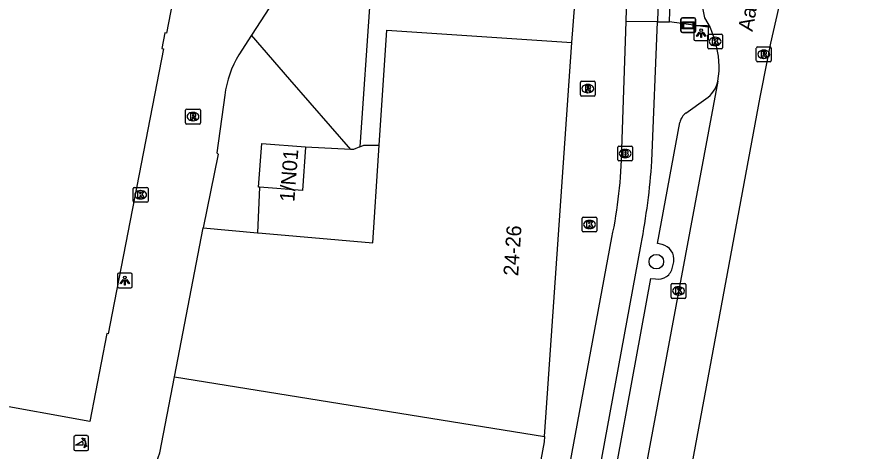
# Model space of a CAD drawing. Extents: x 161402 to 161933, y 381650 to 382313.
# Drawn here: x 161869.9 to 161926.7, y 382046.6 to 382075.9 of the extents above; entities that cross this region are included whole.
import ezdxf

# ---------------------------------------------------------------- set-up
doc = ezdxf.new("R2010")
doc.units = 0
for name, color, linetype in [('IMGEO_Boom', 7, 'Continuous'), ('IMGEO_Brandkraan', 7, 'Continuous'), ('IMGEO_Fietspad_gesloten', 7, 'Continuous'), ('IMGEO_Fietspad_open', 7, 'Continuous'), ('IMGEO_Kolk', 7, 'Continuous'), ('IMGEO_Lichtpunt', 7, 'Continuous'), ('IMGEO_Openbare_ruimte_label', 7, 'Continuous'), ('IMGEO_OVBaan_gesloten', 7, 'Continuous'), ('IMGEO_Pand', 7, 'Continuous'), ('IMGEO_Pand_nummerreeks', 7, 'Continuous'), ('IMGEO_Parkeervlak_open', 7, 'Continuous'), ('IMGEO_Poller', 7, 'Continuous'), ('IMGEO_Reclamebord', 7, 'Continuous'), ('IMGEO_Rijbaan_lokaal_gesloten', 7, 'Continuous'), ('IMGEO_Rijbaan_lokaal_open', 7, 'Continuous'), ('IMGEO_Rioolput', 7, 'Continuous'), ('IMGEO_Verkeerseiland_open', 7, 'Continuous'), ('IMGEO_Voetpad_open', 7, 'Continuous')]:
    doc.layers.add(name, color=color, linetype=linetype)

msp = doc.modelspace()

# ---------------------------------------------------------------- linework, layer by layer
at = {"layer": 'IMGEO_Boom'}
msp.add_circle((161913.065, 382059.379), 0.489, dxfattribs=at)
at = {"layer": 'IMGEO_Brandkraan'}
for p, q in [((161910.461, 382066.251), (161910.461, 382067.103)), ((161910.536, 382067.177), (161911.388, 382067.177)), ((161910.949, 382066.957), (161910.974, 382066.957)), ((161911.462, 382067.103), (161911.462, 382066.251)), ((161910.972, 382066.397), (161910.947, 382066.397)), ((161911.388, 382066.177), (161910.536, 382066.177))]:
    msp.add_line(p, q, dxfattribs=at)
for points in [[(161910.461, 382066.251), (161910.461, 382067.103)], [(161910.536, 382067.177), (161911.388, 382067.177)], [(161911.462, 382067.103), (161911.462, 382066.251)], [(161910.809, 382066.877), (161910.809, 382066.477), (161911.022, 382066.477)], [(161911.04, 382066.877), (161910.809, 382066.877)], [(161910.988, 382066.796), (161910.934, 382066.796), (161910.934, 382066.72)], [(161910.934, 382066.72), (161910.987, 382066.72)], [(161910.996, 382066.644), (161910.934, 382066.644), (161910.934, 382066.563)], [(161910.934, 382066.563), (161910.996, 382066.563)], [(161911.388, 382066.177), (161910.536, 382066.177)]]:
    msp.add_lwpolyline(points, dxfattribs=at)
for centre, radius, start, end in [((161910.538, 382067.101), 0.0765, 91.552, 178.448), ((161910.538, 382067.101), 0.0765, 91.552, 178.448), ((161911.386, 382067.101), 0.0765, 1.552, 88.448), ((161911.386, 382067.101), 0.0765, 1.552, 88.448), ((161910.989, 382066.758), 0.0379, 267.8285, 90.9355), ((161910.997, 382066.603), 0.0404, 269.8759, 90.5077), ((161911.028, 382066.728), 0.251, 268.6676, 293.5347), ((161911.044, 382066.732), 0.145, 59.4692, 91.5367), ((161911.069, 382066.779), 0.0922, 285.5137, 58.1501), ((161911.074, 382066.587), 0.105, 301.3115, 78.989), ((161910.538, 382066.253), 0.0765, 181.552, 268.448), ((161910.538, 382066.253), 0.0765, 181.552, 268.448), ((161911.386, 382066.253), 0.0765, 271.552, 358.448), ((161911.386, 382066.253), 0.0765, 271.552, 358.448)]:
    msp.add_arc(centre, radius, start, end, dxfattribs=at)
for centre, major_axis, ratio, start_param, end_param in [((161910.948, 382066.677), (-0.387, 0.002), 0.722429, 4.712389, 7.853982), ((161910.973, 382066.677), (-0.39, 0.002), 0.717154, 1.570796, 4.712389)]:
    msp.add_ellipse(centre, major_axis=major_axis, ratio=ratio, start_param=start_param, end_param=end_param, dxfattribs=at)
at = {"layer": 'IMGEO_Fietspad_gesloten'}
for points in [[(161910.741, 382066.974), (161911.019, 382075.595)], [(161913.149, 382075.567), (161911.019, 382075.595)], [(161912.769, 382066.155), (161913.149, 382075.567)], [(161887.89, 381941.593), (161898.752, 382000), (161905.702, 382037.375), (161910.061, 382061.001)], [(161869.899, 381834.602), (161881.54, 381896.271), (161882.623, 381902.093), (161888.398, 381933.147), (161890.059, 381942.083), (161900.83, 382000), (161908.061, 382038.88), (161912.039, 382060.567)]]:
    msp.add_lwpolyline(points, dxfattribs=at)
for centre, radius, start, end in [((161879.075, 382067.554), 31.672, 348.0592, 358.9509), ((161864.289, 382069.647), 48.606, 349.2338, 355.8806)]:
    msp.add_arc(centre, radius, start, end, dxfattribs=at)
at = {"layer": 'IMGEO_Fietspad_open'}
for points in [[(161911.019, 382075.595), (161911.485, 382092.573), (161911.516, 382094.566), (161911.423, 382100.579), (161910.052, 382144.744)], [(161912.16, 382144.813), (161912.252, 382141.473), (161913.518, 382100.778), (161913.546, 382089.832), (161913.149, 382075.567)]]:
    msp.add_lwpolyline(points, dxfattribs=at)
at = {"layer": 'IMGEO_Kolk'}
for p, q in [((161916.532, 382073.821), (161916.532, 382074.673)), ((161916.607, 382074.747), (161917.459, 382074.747)), ((161917.02, 382074.527), (161917.045, 382074.527)), ((161917.533, 382074.673), (161917.533, 382073.821)), ((161917.459, 382073.747), (161916.607, 382073.747)), ((161917.043, 382073.967), (161917.018, 382073.967)), ((161877.739, 382063.468), (161877.739, 382064.32)), ((161877.814, 382064.394), (161878.666, 382064.394)), ((161878.227, 382064.174), (161878.252, 382064.174)), ((161878.74, 382064.32), (161878.74, 382063.468)), ((161878.25, 382063.614), (161878.225, 382063.614)), ((161878.666, 382063.394), (161877.814, 382063.394)), ((161908.13, 382062.389), (161908.982, 382062.389)), ((161908.055, 382061.463), (161908.055, 382062.315)), ((161908.543, 382062.169), (161908.568, 382062.169)), ((161909.056, 382062.315), (161909.056, 382061.463)), ((161908.982, 382061.389), (161908.13, 382061.389)), ((161908.566, 382061.609), (161908.541, 382061.609)), ((161914.066, 382056.977), (161914.066, 382057.829)), ((161914.141, 382057.903), (161914.993, 382057.903)), ((161915.067, 382057.829), (161915.067, 382056.977)), ((161914.554, 382057.683), (161914.579, 382057.683)), ((161914.993, 382056.903), (161914.141, 382056.903)), ((161914.577, 382057.123), (161914.552, 382057.123))]:
    msp.add_line(p, q, dxfattribs=at)
for points in [[(161916.532, 382073.821), (161916.532, 382074.673)], [(161916.607, 382074.747), (161917.459, 382074.747)], [(161916.853, 382074.447), (161916.976, 382074.447), (161916.976, 382074.296), (161917.106, 382074.447), (161917.27, 382074.447), (161917.124, 382074.296), (161917.277, 382074.047), (161917.125, 382074.047), (161917.04, 382074.211), (161916.976, 382074.144), (161916.976, 382074.047), (161916.853, 382074.047), (161916.853, 382074.447)], [(161917.533, 382074.673), (161917.533, 382073.821)], [(161917.459, 382073.747), (161916.607, 382073.747)], [(161877.739, 382063.468), (161877.739, 382064.32)], [(161877.814, 382064.394), (161878.666, 382064.394)], [(161878.06, 382064.094), (161878.183, 382064.094), (161878.183, 382063.943), (161878.313, 382064.094), (161878.477, 382064.094), (161878.331, 382063.943), (161878.484, 382063.694), (161878.332, 382063.694), (161878.247, 382063.858), (161878.183, 382063.791), (161878.183, 382063.694), (161878.06, 382063.694), (161878.06, 382064.094)], [(161878.74, 382064.32), (161878.74, 382063.468)], [(161878.666, 382063.394), (161877.814, 382063.394)], [(161908.13, 382062.389), (161908.982, 382062.389)], [(161908.055, 382061.463), (161908.055, 382062.315)], [(161908.376, 382062.089), (161908.499, 382062.089), (161908.499, 382061.938), (161908.629, 382062.089), (161908.793, 382062.089), (161908.647, 382061.938), (161908.8, 382061.689), (161908.648, 382061.689), (161908.563, 382061.853), (161908.499, 382061.786), (161908.499, 382061.689), (161908.376, 382061.689), (161908.376, 382062.089)], [(161909.056, 382062.315), (161909.056, 382061.463)], [(161908.982, 382061.389), (161908.13, 382061.389)], [(161914.066, 382056.977), (161914.066, 382057.829)], [(161914.141, 382057.903), (161914.993, 382057.903)], [(161915.067, 382057.829), (161915.067, 382056.977)], [(161914.387, 382057.603), (161914.51, 382057.603), (161914.51, 382057.452), (161914.64, 382057.603), (161914.804, 382057.603), (161914.658, 382057.452), (161914.811, 382057.203), (161914.659, 382057.203), (161914.574, 382057.367), (161914.51, 382057.3), (161914.51, 382057.203), (161914.387, 382057.203), (161914.387, 382057.603)], [(161914.993, 382056.903), (161914.141, 382056.903)]]:
    msp.add_lwpolyline(points, dxfattribs=at)
for centre, start, end in [((161916.609, 382074.671), 91.552, 178.448), ((161916.609, 382074.671), 91.552, 178.448), ((161917.457, 382074.671), 1.552, 88.448), ((161917.457, 382074.671), 1.552, 88.448), ((161916.609, 382073.823), 181.552, 268.448), ((161916.609, 382073.823), 181.552, 268.448), ((161917.457, 382073.823), 271.552, 358.448), ((161917.457, 382073.823), 271.552, 358.448), ((161877.816, 382064.318), 91.552, 178.448), ((161877.816, 382064.318), 91.552, 178.448), ((161878.664, 382064.318), 1.552, 88.448), ((161878.664, 382064.318), 1.552, 88.448), ((161877.816, 382063.47), 181.552, 268.448), ((161877.816, 382063.47), 181.552, 268.448), ((161878.664, 382063.47), 271.552, 358.448), ((161878.664, 382063.47), 271.552, 358.448), ((161908.132, 382062.313), 91.552, 178.448), ((161908.132, 382062.313), 91.552, 178.448), ((161908.98, 382062.313), 1.552, 88.448), ((161908.98, 382062.313), 1.552, 88.448), ((161908.132, 382061.465), 181.552, 268.448), ((161908.132, 382061.465), 181.552, 268.448), ((161908.98, 382061.465), 271.552, 358.448), ((161908.98, 382061.465), 271.552, 358.448), ((161914.143, 382057.827), 91.552, 178.448), ((161914.143, 382057.827), 91.552, 178.448), ((161914.991, 382057.827), 1.552, 88.448), ((161914.991, 382057.827), 1.552, 88.448), ((161914.143, 382056.979), 181.552, 268.448), ((161914.143, 382056.979), 181.552, 268.448), ((161914.991, 382056.979), 271.552, 358.448), ((161914.991, 382056.979), 271.552, 358.448)]:
    msp.add_arc(centre, 0.0765, start, end, dxfattribs=at)
for centre, major_axis, ratio, start_param, end_param in [((161917.019, 382074.247), (-0.387, 0.002), 0.722429, 4.712389, 7.853982), ((161917.044, 382074.247), (-0.39, 0.002), 0.717154, 1.570796, 4.712389), ((161878.226, 382063.894), (-0.387, 0.002), 0.722429, 4.712389, 7.853982), ((161878.251, 382063.894), (-0.39, 0.002), 0.717154, 1.570796, 4.712389), ((161908.542, 382061.889), (-0.387, 0.002), 0.722429, 4.712389, 7.853982), ((161908.567, 382061.889), (-0.39, 0.002), 0.717154, 1.570796, 4.712389), ((161914.553, 382057.403), (-0.387, 0.002), 0.722429, 4.712389, 7.853982), ((161914.578, 382057.403), (-0.39, 0.002), 0.717154, 1.570796, 4.712389)]:
    msp.add_ellipse(centre, major_axis=major_axis, ratio=ratio, start_param=start_param, end_param=end_param, dxfattribs=at)
at = {"layer": 'IMGEO_Lichtpunt'}
for p, q in [((161915.593, 382075.209), (161915.593, 382074.402)), ((161915.593, 382075.209), (161915.593, 382074.402)), ((161916.495, 382075.304), (161915.687, 382075.304)), ((161916.495, 382075.304), (161915.687, 382075.304)), ((161916.589, 382074.402), (161916.589, 382075.209)), ((161916.589, 382074.402), (161916.589, 382075.209)), ((161915.687, 382074.308), (161916.495, 382074.308)), ((161915.687, 382074.308), (161916.495, 382074.308)), ((161876.677, 382058.507), (161876.677, 382057.7)), ((161876.677, 382058.507), (161876.677, 382057.7)), ((161877.579, 382058.602), (161876.771, 382058.602)), ((161877.579, 382058.602), (161876.771, 382058.602)), ((161877.673, 382057.7), (161877.673, 382058.507)), ((161877.673, 382057.7), (161877.673, 382058.507)), ((161876.771, 382057.606), (161877.579, 382057.606)), ((161876.771, 382057.606), (161877.579, 382057.606))]:
    msp.add_line(p, q, dxfattribs=at)
for points in [[(161915.967, 382074.873), (161916.006, 382074.845), (161915.818, 382074.583), (161915.78, 382074.61), (161915.967, 382074.873)], [(161916.179, 382074.845), (161916.217, 382074.872), (161916.404, 382074.61), (161916.365, 382074.582), (161916.179, 382074.845)], [(161916.069, 382074.825), (161916.116, 382074.825), (161916.116, 382074.503), (161916.069, 382074.503), (161916.069, 382074.825)], [(161877.051, 382058.171), (161877.09, 382058.143), (161876.902, 382057.881), (161876.864, 382057.908), (161877.051, 382058.171)], [(161877.153, 382058.123), (161877.2, 382058.123), (161877.2, 382057.801), (161877.153, 382057.801), (161877.153, 382058.123)], [(161877.263, 382058.143), (161877.301, 382058.17), (161877.488, 382057.908), (161877.449, 382057.88), (161877.263, 382058.143)]]:
    msp.add_lwpolyline(points, dxfattribs=at)
for centre in [(161916.092, 382075.007), (161877.176, 382058.305)]:
    msp.add_circle(centre, 0.0994, dxfattribs=at)
for centre, start, end in [((161915.687, 382075.209), 90, 180), ((161915.687, 382075.209), 90, 180), ((161916.495, 382075.209), 0, 90), ((161916.495, 382075.209), 0, 90), ((161915.687, 382074.402), 180, 270), ((161915.687, 382074.402), 180, 270), ((161916.495, 382074.402), 270, 0), ((161916.495, 382074.402), 270, 360), ((161876.771, 382058.507), 90, 180), ((161876.771, 382058.507), 90, 180), ((161877.579, 382058.507), 0, 90), ((161877.579, 382058.507), 0, 90), ((161876.771, 382057.7), 180, 270), ((161876.771, 382057.7), 180, 270), ((161877.579, 382057.7), 270, 0), ((161877.579, 382057.7), 270, 360)]:
    msp.add_arc(centre, 0.0946, start, end, dxfattribs=at)
at = {"layer": 'IMGEO_OVBaan_gesloten'}
msp.add_lwpolyline([(161894.174, 381930.698), (161920.066, 382070.485), (161920.568, 382072.989), (161920.797, 382074.121), (161926.695, 382099.95)], dxfattribs=at)
at = {"layer": 'IMGEO_Pand'}
for points in [[(161881.604, 382083.709), (161880.846, 382079.728), (161880.941, 382079.709), (161879.984, 382074.802), (161879.866, 382074.825), (161879.674, 382073.772), (161879.777, 382073.754), (161876.327, 382055.897), (161876.056, 382054.517), (161875.966, 382054.535), (161874.803, 382048.597), (161867.831, 382049.852)], [(161894.356, 382067.242), (161894.871, 382075.011), (161907.356, 382074.185)], [(161905.504, 382047.572), (161907.356, 382074.185)], [(161886.126, 382061.332), (161886.444, 382061.304), (161893.92, 382060.648), (161894.311, 382066.556), (161894.356, 382067.242)], [(161886.272, 382064.4), (161886.197, 382064.406), (161886.417, 382067.362), (161889.384, 382067.141), (161889.381, 382067.098)], [(161889.381, 382067.098), (161889.164, 382064.185), (161886.272, 382064.4)], [(161880.537, 382051.6), (161882.474, 382061.653)], [(161882.474, 382061.653), (161886.126, 382061.332)], [(161878.423, 382043.323), (161879.548, 382046.468), (161880.537, 382051.6)], [(161880.537, 382051.6), (161905.504, 382047.572)], [(161905.504, 382047.572), (161905.48, 382047.22), (161903.899, 382038.59)]]:
    msp.add_lwpolyline(points, dxfattribs=at)
at = {"layer": 'IMGEO_Parkeervlak_open'}
for points in [[(161915.065, 382069.413), (161916.415, 382070.367)], [(161913.448, 382060.543), (161913.141, 382060.602), (161914.659, 382068.781)], [(161914.151, 382059.011), (161914.248, 382059.368)], [(161909.441, 382038.888), (161909.164, 382038.94), (161912.699, 382058.251), (161913.017, 382058.21)]]:
    msp.add_lwpolyline(points, dxfattribs=at)
for centre, radius, start, end in [((161915.343, 382071.952), 1.914, 304.054, 348.2569), ((161915.635, 382068.6), 0.993, 125.0548, 169.5114), ((161913.206, 382059.518), 1.053, 351.8071, 76.691), ((161913.193, 382059.164), 0.97, 259.5654, 350.9054)]:
    msp.add_arc(centre, radius, start, end, dxfattribs=at)
at = {"layer": 'IMGEO_Poller'}
for p, q in [((161874.634, 382047.632), (161873.826, 382047.632)), ((161874.634, 382047.632), (161873.826, 382047.632)), ((161873.732, 382047.537), (161873.732, 382046.73)), ((161873.732, 382047.537), (161873.732, 382046.73)), ((161874.728, 382046.73), (161874.728, 382047.537)), ((161874.728, 382046.73), (161874.728, 382047.537)), ((161873.826, 382046.635), (161874.634, 382046.635)), ((161873.826, 382046.635), (161874.634, 382046.635))]:
    msp.add_line(p, q, dxfattribs=at)
for points in [[(161874.367, 382046.988), (161873.854, 382046.988), (161874.284, 382047.263)], [(161874.411, 382047.361), (161874.399, 382047.288), (161874.274, 382047.493)], [(161874.274, 382047.493), (161874.505, 382047.427), (161874.434, 382047.395)], [(161874.427, 382046.816), (161874.493, 382047.047), (161874.523, 382046.979)], [(161874.559, 382046.952), (161874.631, 382046.941), (161874.427, 382046.816)]]:
    msp.add_lwpolyline(points, dxfattribs=at)
for centre, radius, start, end in [((161873.826, 382047.537), 0.0946, 90, 180), ((161873.826, 382047.537), 0.0946, 90, 180), ((161874.634, 382047.537), 0.0946, 0, 90), ((161874.634, 382047.537), 0.0946, 0, 90), ((161874.039, 382047.038), 0.332, 351.3247, 42.4854), ((161874.053, 382047.048), 0.476, 351.7527, 41.1691), ((161874.053, 382047.048), 0.516, 349.3569, 42.2912), ((161873.826, 382046.73), 0.0946, 180, 270), ((161873.826, 382046.73), 0.0946, 180, 270), ((161874.634, 382046.73), 0.0946, 270, 0), ((161874.634, 382046.73), 0.0946, 270, 0)]:
    msp.add_arc(centre, radius, start, end, dxfattribs=at)
at = {"layer": 'IMGEO_Reclamebord'}
for p, q in [((161914.729, 382074.94), (161914.729, 382075.74)), ((161914.729, 382075.74), (161914.729, 382074.94)), ((161914.829, 382075.84), (161915.619, 382075.84)), ((161915.619, 382075.84), (161914.829, 382075.84)), ((161915.719, 382075.74), (161915.719, 382074.94)), ((161915.719, 382074.94), (161915.719, 382075.74)), ((161915.619, 382074.84), (161914.829, 382074.84)), ((161914.829, 382074.84), (161915.619, 382074.84))]:
    msp.add_line(p, q, dxfattribs=at)
for points in [[(161914.83, 382075.572), (161915.618, 382075.572), (161915.618, 382075.108), (161914.83, 382075.108), (161914.83, 382075.572)], [(161914.895, 382075.507), (161914.895, 382075.173), (161915.553, 382075.173), (161915.553, 382075.507), (161914.895, 382075.507)]]:
    msp.add_lwpolyline(points, dxfattribs=at)
for centre, start, end in [((161914.829, 382075.74), 90, 180), ((161914.829, 382075.74), 90, 180), ((161915.619, 382075.74), 0, 90), ((161915.619, 382075.74), 360, 90), ((161914.829, 382074.94), 180, 270), ((161914.829, 382074.94), 180, 270), ((161915.619, 382074.94), 270, 0), ((161915.619, 382074.94), 270, 0)]:
    msp.add_arc(centre, 0.1, start, end, dxfattribs=at)
at = {"layer": 'IMGEO_Rijbaan_lokaal_gesloten'}
for points in [[(161919.101, 382094.04), (161916.164, 382076.625), (161916.325, 382075.85), (161916.704, 382075.178)], [(161916.704, 382075.178), (161917.035, 382074.248)], [(161917.217, 382071.563), (161910.924, 382037.806), (161903.912, 382000), (161894.985, 381951.871)]]:
    msp.add_lwpolyline(points, dxfattribs=at)
msp.add_arc((161911.814, 382072.545), 5.492, 349.695, 18.0606, dxfattribs=at)
at = {"layer": 'IMGEO_Rijbaan_lokaal_open'}
for points in [[(161913.954, 382075.562), (161914.223, 382084.227)], [(161887.537, 382077.461), (161885.72, 382074.668)], [(161916.704, 382075.178), (161913.954, 382075.562)], [(161885.72, 382074.668), (161884.863, 382073.351)], [(161883.925, 382070.629), (161883.395, 382066.737), (161883.474, 382066.647), (161882.474, 382061.653)]]:
    msp.add_lwpolyline(points, dxfattribs=at)
msp.add_arc((161891.134, 382069.667), 7.273, 149.5698, 172.4024, dxfattribs=at)
at = {"layer": 'IMGEO_Rioolput'}
for p, q in [((161919.818, 382072.952), (161919.818, 382073.804)), ((161919.893, 382073.878), (161920.745, 382073.878)), ((161920.819, 382073.804), (161920.819, 382072.952)), ((161920.306, 382073.658), (161920.331, 382073.658)), ((161920.745, 382072.878), (161919.893, 382072.878)), ((161920.329, 382073.098), (161920.304, 382073.098)), ((161907.937, 382070.634), (161907.937, 382071.486)), ((161908.012, 382071.56), (161908.864, 382071.56)), ((161908.938, 382071.486), (161908.938, 382070.634)), ((161908.425, 382071.34), (161908.45, 382071.34)), ((161908.864, 382070.56), (161908.012, 382070.56)), ((161908.448, 382070.78), (161908.423, 382070.78)), ((161881.278, 382068.747), (161881.278, 382069.599)), ((161881.353, 382069.673), (161882.205, 382069.673)), ((161881.766, 382069.453), (161881.791, 382069.453)), ((161882.279, 382069.599), (161882.279, 382068.747)), ((161882.205, 382068.673), (161881.353, 382068.673)), ((161881.789, 382068.893), (161881.764, 382068.893))]:
    msp.add_line(p, q, dxfattribs=at)
for points in [[(161919.818, 382072.952), (161919.818, 382073.804)], [(161919.893, 382073.878), (161920.745, 382073.878)], [(161920.819, 382073.804), (161920.819, 382072.952)], [(161920.407, 382073.576), (161920.155, 382073.578), (161920.155, 382073.178)], [(161920.155, 382073.178), (161920.279, 382073.178), (161920.279, 382073.34), (161920.29, 382073.34)], [(161920.333, 382073.497), (161920.279, 382073.497), (161920.279, 382073.416)], [(161920.279, 382073.416), (161920.331, 382073.416)], [(161920.337, 382073.311), (161920.408, 382073.178), (161920.548, 382073.178), (161920.483, 382073.304)], [(161920.745, 382072.878), (161919.893, 382072.878)], [(161907.937, 382070.634), (161907.937, 382071.486)], [(161908.012, 382071.56), (161908.864, 382071.56)], [(161908.938, 382071.486), (161908.938, 382070.634)], [(161908.526, 382071.258), (161908.274, 382071.26), (161908.274, 382070.86)], [(161908.274, 382070.86), (161908.398, 382070.86), (161908.398, 382071.022), (161908.409, 382071.022)], [(161908.452, 382071.179), (161908.398, 382071.179), (161908.398, 382071.098)], [(161908.398, 382071.098), (161908.45, 382071.098)], [(161908.456, 382070.993), (161908.527, 382070.86), (161908.667, 382070.86), (161908.602, 382070.986)], [(161908.864, 382070.56), (161908.012, 382070.56)], [(161881.278, 382068.747), (161881.278, 382069.599)], [(161881.353, 382069.673), (161882.205, 382069.673)], [(161881.867, 382069.371), (161881.615, 382069.373), (161881.615, 382068.973)], [(161881.793, 382069.292), (161881.739, 382069.292), (161881.739, 382069.211)], [(161881.739, 382069.211), (161881.791, 382069.211)], [(161882.279, 382069.599), (161882.279, 382068.747)], [(161882.205, 382068.673), (161881.353, 382068.673)], [(161881.615, 382068.973), (161881.739, 382068.973), (161881.739, 382069.135), (161881.75, 382069.135)], [(161881.797, 382069.106), (161881.868, 382068.973), (161882.008, 382068.973), (161881.943, 382069.099)]]:
    msp.add_lwpolyline(points, dxfattribs=at)
for centre, radius, start, end in [((161919.895, 382073.802), 0.0765, 91.552, 178.448), ((161919.895, 382073.802), 0.0765, 91.552, 178.448), ((161920.743, 382073.802), 0.0765, 1.552, 88.448), ((161920.743, 382073.802), 0.0765, 1.552, 88.448), ((161920.289, 382073.287), 0.0533, 26.0293, 88.6989), ((161920.315, 382073.605), 0.19, 274.7715, 282.9687), ((161920.339, 382073.401), 0.0964, 77.0061, 93.1865), ((161920.353, 382073.458), 0.0378, 276.6634, 79.6772), ((161920.406, 382073.466), 0.109, 350.3612, 89.416), ((161920.404, 382073.466), 0.112, 277.5842, 350.9817), ((161920.388, 382073.251), 0.108, 29.5134, 73.7905), ((161919.895, 382072.954), 0.0765, 181.552, 268.448), ((161919.895, 382072.954), 0.0765, 181.552, 268.448), ((161920.743, 382072.954), 0.0765, 271.552, 358.448), ((161920.743, 382072.954), 0.0765, 271.552, 358.448), ((161908.014, 382071.484), 0.0765, 91.552, 178.448), ((161908.014, 382071.484), 0.0765, 91.552, 178.448), ((161908.862, 382071.484), 0.0765, 1.552, 88.448), ((161908.862, 382071.484), 0.0765, 1.552, 88.448), ((161908.408, 382070.969), 0.0533, 26.0293, 88.6989), ((161908.434, 382071.287), 0.19, 274.7715, 282.9687), ((161908.458, 382071.083), 0.0964, 77.0061, 93.1865), ((161908.472, 382071.14), 0.0378, 276.6634, 79.6772), ((161908.525, 382071.148), 0.109, 350.3612, 89.416), ((161908.523, 382071.148), 0.112, 277.5842, 350.9817), ((161908.507, 382070.933), 0.108, 29.5134, 73.7905), ((161908.014, 382070.636), 0.0765, 181.552, 268.448), ((161908.014, 382070.636), 0.0765, 181.552, 268.448), ((161908.862, 382070.636), 0.0765, 271.552, 358.448), ((161908.862, 382070.636), 0.0765, 271.552, 358.448), ((161881.355, 382069.597), 0.0765, 91.552, 178.448), ((161881.355, 382069.597), 0.0765, 91.552, 178.448), ((161881.775, 382069.4), 0.19, 274.7715, 282.9687), ((161881.799, 382069.196), 0.0964, 77.0061, 93.1865), ((161881.813, 382069.253), 0.0378, 276.6634, 79.6772), ((161881.866, 382069.261), 0.109, 350.3612, 89.416), ((161881.864, 382069.261), 0.112, 277.5842, 350.9817), ((161882.203, 382069.597), 0.0765, 1.552, 88.448), ((161882.203, 382069.597), 0.0765, 1.552, 88.448), ((161881.355, 382068.749), 0.0765, 181.552, 268.448), ((161881.355, 382068.749), 0.0765, 181.552, 268.448), ((161881.749, 382069.082), 0.0533, 26.0293, 88.6989), ((161881.848, 382069.046), 0.108, 29.5134, 73.7905), ((161882.203, 382068.749), 0.0765, 271.552, 358.448), ((161882.203, 382068.749), 0.0765, 271.552, 358.448)]:
    msp.add_arc(centre, radius, start, end, dxfattribs=at)
for centre, major_axis, ratio, start_param, end_param in [((161920.305, 382073.378), (-0.387, 0.002), 0.722429, 4.712389, 7.853982), ((161920.33, 382073.378), (-0.39, 0.002), 0.717154, 1.570796, 4.712389), ((161908.424, 382071.06), (-0.387, 0.002), 0.722429, 4.712389, 7.853982), ((161908.449, 382071.06), (-0.39, 0.002), 0.717154, 1.570796, 4.712389), ((161881.765, 382069.173), (-0.387, 0.002), 0.722429, 4.712389, 7.853982), ((161881.79, 382069.173), (-0.39, 0.002), 0.717154, 1.570796, 4.712389)]:
    msp.add_ellipse(centre, major_axis=major_axis, ratio=ratio, start_param=start_param, end_param=end_param, dxfattribs=at)
at = {"layer": 'IMGEO_Verkeerseiland_open'}
msp.add_lwpolyline([(161913.149, 382075.567), (161913.954, 382075.562)], dxfattribs=at)
at = {"layer": 'IMGEO_Voetpad_open'}
for points in [[(161895.501, 382077.17), (161893.731, 382077.231), (161893.044, 382067.129)], [(161907.356, 382074.185), (161907.56, 382076.762)], [(161892.436, 382066.953), (161888.323, 382071.67), (161885.72, 382074.668)], [(161892.436, 382066.953), (161889.381, 382067.098)], [(161893.044, 382067.129), (161892.619, 382066.944), (161892.436, 382066.953)], [(161893.044, 382067.129), (161893.307, 382067.242), (161894.356, 382067.242)], [(161886.272, 382064.4), (161886.126, 382061.332)]]:
    msp.add_lwpolyline(points, dxfattribs=at)

# ---------------------------------------------------------------- texts
at = {"layer": 'IMGEO_Openbare_ruimte_label'}
msp.add_text('Aalsterweg', height=1, rotation=79.5773, dxfattribs=at).set_placement((161919.558, 382074.882))
at = {"layer": 'IMGEO_Pand_nummerreeks'}
for s, rotation, p in [('1/N01', 85.5483, (161888.62, 382063.384)), ('24-26', 86.0182, (161903.731, 382058.384))]:
    msp.add_text(s, height=1, rotation=rotation, dxfattribs=at).set_placement(p)

doc.saveas('drawing.dxf')
